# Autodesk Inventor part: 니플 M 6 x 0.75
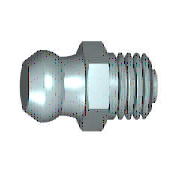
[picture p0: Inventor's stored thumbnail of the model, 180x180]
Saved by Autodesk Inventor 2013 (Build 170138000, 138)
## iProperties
IsCustomPart: 1
Created: 2012-02
Part Number: 니플 M 6 x 0.75
Material: 강철, 연강
Description: 윤활 니플, 원추 유형 A
Document SubType Name: Modeling
Standard: JIS B 1575
Designer: mduedu
Standards Organization: JIS
Language: ko-KR
Size Designation: MT 6 x 0.75
Categories: <MemberInstance><Categories><Category DisplayName="기타 부품" InternalName="5aa15e00-363f-49f2-933f-16f664388e3f" Mnemonic="OTHER"><Category DisplayName="그리스 부속품" I
Density: 1 g/cm^3
Author: mduedu
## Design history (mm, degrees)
sketch "스케치1"
  geometry: L1 (-8.8, 0)-(-8.8, 2.4); L2 (-8.8, 2.4)-(-7.335, 3.202); L3 (-8.8, 0)-(4.7, 0); L4 (4.7, 0)-(4.7, 1.5); L5 (4.7, 1.5)-(4, 1.5); L6 (4, 1.5)-(4, 3); L7 (4, 3)-(0, 3); L8 (-11.5, 0)-(7.4, 0) reference; L9 (0, -1.733)-(0, 10.398) reference; L10 (-3, 3.5)-(0, 3.5); L11 (0, 3.5)-(0, 3); A1 r 3.3 centre (-6.535, 0) between (-4.789, 2.8) and (-7.335, 3.202); A2 r 6 centre (-6.053, 8.665) between (-4.789, 2.8) and (-3, 3.5)
  constraints: 18 end point, 5 perpendicular, 4 point on circle, 2 centre point, 2 parallel, 2 point on line, 1 collinear, 1 vertical
  dimensions: "d0" = 13.5 distance between parallel lines of L1 L4 (= GL); "d1" = 5.6 diameter of A1.start L3 (= KGB2); "d2" = 0.7 distance between parallel lines of L4 L6 (= PHH); "d3" = 3 diameter of L5 L3 (= 0.5 x NND); "d4" = 6 diameter of L7 L3 (= NND); "d5" = 6.6 dimension on A1 L3 (= KR); "d6" = 4.8 diameter of L1.end L3 (= KGB1); "d7" = 6 radius of A2 (= RBN); "d11" = 7 diameter of L10.start L3 (= SW); "d14" = 3 distance of L10.start L10.end (= KOH); "d15" = 4 distance between parallel lines of L6 L11 (= NLG); "d61" = 7.33505 distance from line of L9 L2.end (computed from KGB1, KR, PHH, GL, NLG, VERS); "d62" = 6.53505 distance from line of L9 A1.centre (computed from NLG, GL, PHH, KR, KGB1)
revolve "본체" sketch "스케치1" stored, may be unused: angle "d25" = 90 deg
sketch "스케치2"
  geometry: L1 (2.021, 3.5)-(4.041, 0); L2 (4.041, 0)-(2.021, -3.5); L3 (2.021, -3.5)-(-2.021, -3.5); L4 (-2.021, -3.5)-(-4.041, 0); L5 (-4.041, 0)-(-2.021, 3.5); L6 (-2.021, 3.5)-(2.021, 3.5); C1 r 3.5 at (0, 0) reference; 1 further point
  constraints: 12 end point, 1 coincident, 1 horizontal, 1 tangent, 11 other
extrude "머리" join sketch "스케치2" distance "d17" = 3 (= KOH); taper "d18" = 0 deg
sketch "스케치3"
  geometry: L1 (2.687, 4.041)-(3, 4.041); L2 (3, 4.041)-(3, 3.5); L3 (3, 3.5)-(2.687, 4.041); L4 (0.313, 4.041)-(0, 4.041); L5 (0, 4.041)-(0, 3.5); L6 (0, 3.5)-(0.313, 4.041); L7 (3.6, 0)-(-0.6, 0) reference; L8 (0, 4.041)-(0, 2.021) reference; L9 (0, 4.041)-(3, 4.041) reference; L10 (3, 3.031)-(3, 4.041) reference
  constraints: 12 end point, 4 collinear, 3 perpendicular, 1 horizontal
  dimensions: "d19" = 3.5 distance from line of L5.end L7 (= 0.5 x SW); "d20" = 3.5 distance from line of L2.end L7 (= 0.5 x SW); "d21" = 30 deg angle of L6 L5; "d22" = 30 deg angle of L2 L3
revolve "모따기1" sketch "스케치3" stored, may be unused: angle "d56" = 90 deg
body "Solid1"
fillet "모깎기1" dims "d8" = 0.2 (= RR)
feature "스레드1" dims "d9" = 3.53991 (= NLG - GAL), "d10" = 0
chamfer "모따기2" distance "d23" = 0.46009 (= -0.5 x GD1 + 0.5 x NND); stored, may be unused: angle "d24" = 45 deg, second distance "d59" = 0.46009 (= -0.5 x GD1 + 0.5 x NND)
other parameters: "NLG" = 4 [user parameter; used in 4 equation terms], "GL" = 13.5 [user parameter; used in 3 equation terms], "NND" = 6 [user parameter; used in 4 equation terms], "KGB1" = 4.8 [user parameter; used in 3 equation terms], "KGB2" = 5.6 [user parameter; used in 1 equation term], "VERS" = 0.8 [user parameter; used in 1 equation term], "KR" = 6.6 [user parameter; used in 3 equation terms], "RBN" = 6 [user parameter; used in 1 equation term], "SW" = 7 [user parameter; used in 3 equation terms], "KOH" = 3 [user parameter; used in 2 equation terms], "GAL" = 0.46009 (= 0.61345 x PTC) [user parameter; used in 1 equation term], "FAWI" = 45 deg [user parameter], "PHH" = 0.7 [user parameter; used in 3 equation terms], "GD1" = 5.07983 (= THREADDIA - 1.2269 x PTC) [user parameter; used in 2 equation terms], "RR" = 0.2 [user parameter; used in 1 equation term], "d12" = 0, "d13" = 0, "GUL" = 0.46009 (= 0.61345 x PTC) [user parameter], "TPU" = 13.33333 (computed from PTC) [user parameter], "DULO" = 1.5 [user parameter], "PTC" = 0.75 [user parameter; used in 4 equation terms], "GEL" = 4 [user parameter], "THREADDIA" = 6 [user parameter; used in 1 equation term], "TOA" = 30 deg [user parameter]
